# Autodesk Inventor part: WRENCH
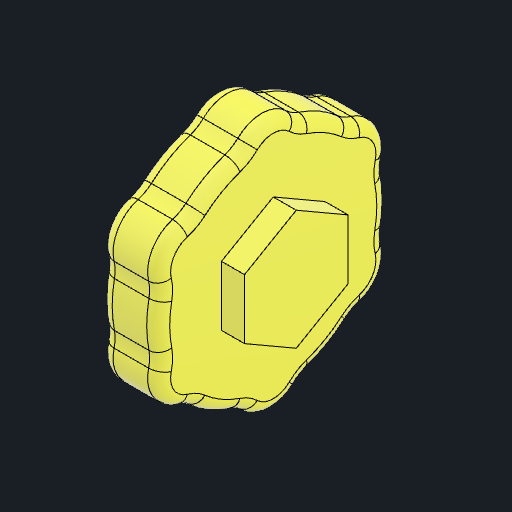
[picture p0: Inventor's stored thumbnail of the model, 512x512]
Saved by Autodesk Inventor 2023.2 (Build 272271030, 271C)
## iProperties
Created: 2022-12
Part Number: WRENCH
Material: Generic
Document SubType Name: Modeling
Designer: AR
Mass: 12.8297 g
Surface Area: 44.8709 cm^2
Volume: 12.8297 cm^3
Density: 1 g/cm^3
Appearance: Smooth - Purple
Author: AR
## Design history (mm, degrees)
derived "_2 SPOOL CORD WRAP MP.ipt"
feature "WRENCH::_2 SPOOL CORD WRAP MP.ipt" dims "d0" = 10
tag "TaggingFeature1"
node "WRENCH"
